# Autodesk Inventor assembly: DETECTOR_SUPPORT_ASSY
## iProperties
Shininess: 64.0
Length Units: 11272
Angle Units: 11279
Time Units: 11290
Mass Units: 11286
Length Display Precision: 3
Angle Display Precision: 2
Compacted: True
Part Number: DETECTOR_SUPPORT_ASSY
Document SubType Name: Assembly
Created: 2004-08
Designer: John Blackburn
Manufacturer: Standard
Standards Organization: Custom
Density: 0.0
Volumn: 0.0
Area: 0.0
PropertySet Name: Model Information
Control State: 0
Master: False
Checked Out: False
Author: John Blackburn
